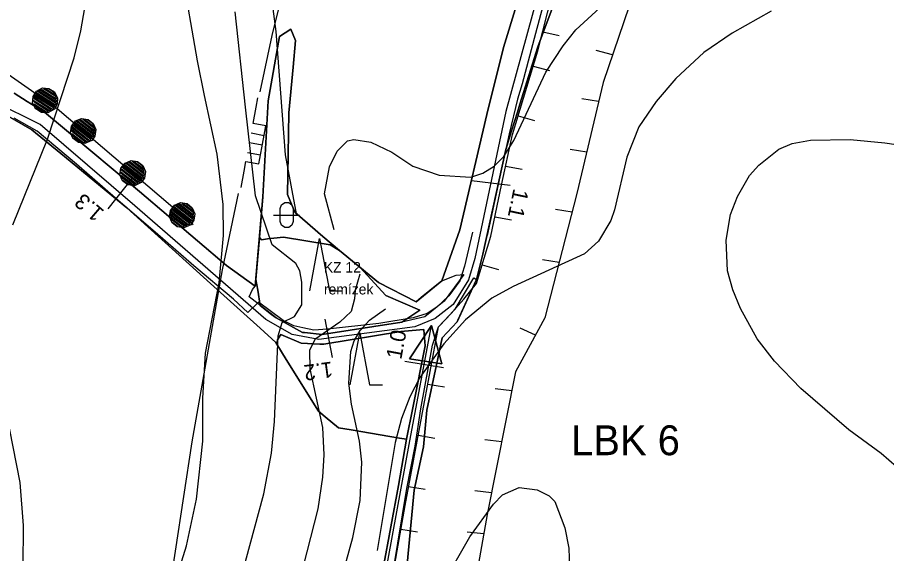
# Model space of a CAD drawing. Extents: x -645676 to -642474, y -1077513 to -1072613.
# Drawn here: x -644258.9 to -643924.4, y -1076253.6 to -1076047.4 of the extents above; entities that cross this region are included whole.
import ezdxf

# ---------------------------------------------------------------- set-up
doc = ezdxf.new("R2010")
doc.units = 0
for name, color, linetype in [('KRAJ_ZELEN_STAV', 7, 'Continuous'), ('Krajinn__zele____popis___stav', 7, 'Continuous'), ('KULTURY_STAV', 7, 'Continuous'), ('KULTURY_ZNACKY', 7, 'Continuous'), ('Lok_ln__biokoridor___navr_en_', 7, 'Continuous'), ('Odvodnen__cesty_pod_lnou_dren_____navr_en_', 7, 'Continuous'), ('Odvodnen__cesty_pr_kopem___navr_en_', 7, 'Continuous'), ('PC_NAVRH', 7, 'Continuous'), ('PC_STAN_NAVRH', 7, 'Continuous'), ('PLYNOVOD', 7, 'Continuous'), ('USES_BK_NAVRH', 7, 'Continuous'), ('USES_IP_NAVRH', 7, 'Continuous'), ('VRSTEVNICE', 7, 'Continuous')]:
    doc.layers.add(name, color=color, linetype=linetype)

# ---------------------------------------------------------------- blocks, each defined once
blk = doc.blocks.new('$944')
blk.add_line((0, 1.5), (0, -1.5))
blk = doc.blocks.new('$920')
for points in [[(0, 0), (-2.8, 1.25), (-2.8, -1.25), (0, 0)], [(-2.8, 1.25), (0, 0), (-2.8, -1.25), (-2.8, 1.25)]]:
    blk.add_lwpolyline(points)
blk = doc.blocks.new('3$0800')
blk.add_lwpolyline([(-0.75, 0), (0, 4), (0.75, 0), (1.75, 0)])
blk = doc.blocks.new('3$1600')
for points in [[(-0.5, 1.5), (-0.4, 1.79), (-0.15, 1.97), (0.16, 1.97), (0.41, 1.79), (0.51, 1.5), (0.51, 0.5), (0.41, 0.21), (0.16, 0.03), (-0.15, 0.03), (-0.4, 0.21), (-0.5, 0.5), (-0.5, 1.5)], [(-1, 1), (0.27, 1), (1, 1)]]:
    blk.add_lwpolyline(points)
blk = doc.blocks.new('2$1030')
blk.add_line((0, 0), (0, -0.5))
blk = doc.blocks.new('6$4100')
blk.add_lwpolyline([(0.19, 0.72), (0.53, 0.53), (0.72, 0.19), (0.72, -0.2), (0.53, -0.54), (0.19, -0.73), (-0.2, -0.73), (-0.54, -0.54), (-0.73, -0.2), (-0.75, 0.12), (-0.54, 0.52), (-0.2, 0.71), (0.19, 0.71), (0.2, 0.67), (-0.2, 0.67), (-0.36, 0.59), (0.36, 0.59), (0.44, 0.51), (-0.44, 0.51), (-0.52, 0.43), (0.52, 0.43), (0.6, 0.35), (-0.6, 0.35), (-0.6, 0.27), (0.6, 0.27), (0.68, 0.19), (-0.59, 0.19), (-0.68, 0.19), (-0.68, 0.11), (0.59, 0.11), (0.68, 0.11), (0.68, 0.03), (-0.59, 0.03), (-0.68, 0.03), (-0.68, -0.05), (0.59, -0.05), (0.68, -0.05), (0.68, -0.13), (-0.59, -0.13), (-0.68, -0.13), (-0.68, -0.21), (0.59, -0.21), (0.68, -0.21), (0.6, -0.29), (-0.6, -0.29), (-0.6, -0.37), (0.6, -0.37), (0.52, -0.45), (-0.52, -0.45), (-0.44, -0.53), (0.44, -0.53), (0.36, -0.61), (-0.36, -0.61), (-0.2, -0.69), (0.2, -0.69)])
blk = doc.blocks.new('6$3520')
for p, q in [((-0.76, 0), (-0.76, -1)), ((0, -1), (0, 0)), ((0.76, 0), (0.76, -1))]:
    blk.add_line(p, q)
blk.add_lwpolyline([(-3.5, 0), (-2.23, 0), (-1.48, 0), (-1.48, -1), (-0.21, -1), (1.06, -1), (1.5, -1), (1.5, 0), (2.77, 0), (3.5, 0)])

msp = doc.modelspace()

# ---------------------------------------------------------------- linework, layer by layer
at = {"layer": 'KRAJ_ZELEN_STAV'}
for points in [[(-644167.35, -1076150.76), (-644164.46, -1076116.34), (-644162.44, -1076079.41), (-644158.08, -1076054.68), (-644153.67, -1076051.97), (-644151.87, -1076056.3), (-644154.44, -1076084.07), (-644154.94, -1076115.51), (-644152.19, -1076122.23), (-644141.33, -1076131.67), (-644119.97, -1076149.38), (-644105.5, -1076156.74), (-644095.59, -1076148.67), (-644090.09, -1076146.58), (-644087.13, -1076146.25), (-644094.66, -1076156.57), (-644102.05, -1076162.51), (-644110.99, -1076164.6), (-644141.58, -1076169.31), (-644149.13, -1076168.54), (-644159.36, -1076162.99), (-644169.66, -1076154.89), (-644168.45, -1076151.98), (-644167.35, -1076150.76)], [(-644114.19, -1076259.66), (-644109.1, -1076228.56), (-644105.85, -1076212.33), (-644103.69, -1076197.94), (-644099.16, -1076173.48), (-644096.83, -1076166.36), (-644090.49, -1076159.63), (-644083.26, -1076147.58), (-644082.23, -1076148.18), (-644089.69, -1076164.46), (-644095.43, -1076170.57), (-644101.31, -1076198.48), (-644102.64, -1076212.56), (-644106.22, -1076229.19), (-644109.17, -1076260.32)]]:
    msp.add_lwpolyline(points, dxfattribs=at)
at = {"layer": 'KULTURY_STAV'}
for points in [[(-644260.19, -1076076.56), (-644255.1, -1076079.71), (-644250.1, -1076082.79), (-644248.52, -1076083.77), (-644240.78, -1076090.23), (-644211.91, -1076114.3), (-644178.41, -1076142.74), (-644167.35, -1076150.76), (-644167.13, -1076148.23), (-644167.13, -1076148.22), (-644166.33, -1076152.32), (-644165.51, -1076158.15), (-644161.1, -1076161.63), (-644159.36, -1076162.99), (-644149.13, -1076168.55), (-644148.47, -1076168.61), (-644141.58, -1076169.31), (-644110.99, -1076164.6), (-644110.97, -1076164.6), (-644104.09, -1076160.01), (-644117.17, -1076154.34), (-644127.14, -1076143.44), (-644119.97, -1076149.38), (-644105.5, -1076156.74), (-644103.46, -1076155.08), (-644100.16, -1076152.39), (-644095.59, -1076148.67), (-644088.67, -1076129.14), (-644078.26, -1076084.73), (-644071.86, -1076058.97), (-644057.9, -1076013.39)], [(-644057.9, -1076013.39), (-644071.86, -1076058.97), (-644078.26, -1076084.73), (-644088.67, -1076129.14), (-644095.59, -1076148.67), (-644100.16, -1076152.39), (-644103.46, -1076155.08), (-644105.5, -1076156.74), (-644119.97, -1076149.38), (-644127.14, -1076143.44), (-644134.92, -1076136.98), (-644134.94, -1076136.97), (-644141.33, -1076131.67), (-644152.19, -1076122.23), (-644154.94, -1076115.51), (-644154.82, -1076107.92), (-644154.44, -1076084.07), (-644152.81, -1076066.52), (-644151.87, -1076056.31), (-644153.67, -1076051.97), (-644158.08, -1076054.68), (-644162.44, -1076079.41), (-644164.47, -1076116.34), (-644165.78, -1076132.02), (-644167.13, -1076148.22), (-644167.13, -1076148.23), (-644167.35, -1076150.76), (-644178.41, -1076142.74), (-644211.91, -1076114.3), (-644240.78, -1076090.23), (-644248.52, -1076083.77), (-644250.1, -1076082.79), (-644255.1, -1076079.71), (-644260.19, -1076076.56)], [(-644048.37, -1076031.2), (-644058.62, -1076058.66), (-644065.52, -1076080.76), (-644066.49, -1076083.86), (-644068.73, -1076091.03), (-644070.97, -1076098.22), (-644079.76, -1076138.38), (-644082.09, -1076147.63), (-644082.23, -1076148.18), (-644085.8, -1076155.97), (-644089.4, -1076163.82), (-644089.69, -1076164.46), (-644093.55, -1076168.57), (-644095.43, -1076170.57), (-644097.64, -1076181.06), (-644101.31, -1076198.48), (-644102.64, -1076212.56), (-644106.22, -1076229.19), (-644109.17, -1076260.32)], [(-644109.17, -1076260.32), (-644106.22, -1076229.19), (-644102.64, -1076212.56), (-644101.31, -1076198.48), (-644097.64, -1076181.06), (-644095.43, -1076170.57), (-644093.55, -1076168.57), (-644089.69, -1076164.46), (-644089.4, -1076163.82), (-644085.8, -1076155.97), (-644082.23, -1076148.18), (-644082.09, -1076147.63), (-644079.76, -1076138.38), (-644070.97, -1076098.22), (-644068.73, -1076091.03), (-644066.49, -1076083.86), (-644065.52, -1076080.76), (-644058.62, -1076058.66), (-644048.37, -1076031.2)], [(-644153.67, -1076051.97), (-644151.87, -1076056.31), (-644152.81, -1076066.52), (-644154.44, -1076084.07), (-644154.82, -1076107.92), (-644154.94, -1076115.51), (-644152.19, -1076122.23), (-644141.33, -1076131.67), (-644134.94, -1076136.97), (-644134.92, -1076136.98), (-644138.54, -1076134.83), (-644156.52, -1076131.95), (-644162.62, -1076132.59), (-644164.97, -1076132.96), (-644165.78, -1076132.02), (-644164.47, -1076116.34), (-644162.44, -1076079.41), (-644158.08, -1076054.68), (-644153.67, -1076051.97)], [(-644118.1, -1076259.16), (-644112.19, -1076227.42), (-644109.13, -1076209.62), (-644106.67, -1076197.52), (-644102.03, -1076173.69), (-644102.49, -1076167.57), (-644102.5, -1076167.41), (-644104.06, -1076167.54), (-644111.38, -1076168.17), (-644140.99, -1076173.09), (-644142.52, -1076173.02), (-644149.64, -1076172.72), (-644157.52, -1076169.4), (-644157.73, -1076169.71), (-644158.81, -1076171.33), (-644159.07, -1076173.02), (-644159.49, -1076172.35), (-644165.51, -1076166.94), (-644173.04, -1076160.17), (-644184.58, -1076149.66), (-644216.77, -1076120.68), (-644242.18, -1076099.78), (-644253.28, -1076090.66), (-644263.37, -1076084.84)], [(-644263.37, -1076084.84), (-644253.28, -1076090.66), (-644242.18, -1076099.78), (-644216.77, -1076120.68), (-644184.58, -1076149.66), (-644173.04, -1076160.17), (-644165.51, -1076166.94), (-644159.49, -1076172.35), (-644159.07, -1076173.02), (-644155.43, -1076178.9), (-644143.05, -1076198.88), (-644140.47, -1076201.01), (-644140.46, -1076201.02), (-644135.28, -1076205.27), (-644130.52, -1076206.06), (-644130.51, -1076206.06), (-644111.8, -1076209.18), (-644109.13, -1076209.62), (-644112.19, -1076227.42), (-644118.1, -1076259.16)], [(-644156.52, -1076131.95), (-644138.54, -1076134.83), (-644134.92, -1076136.98), (-644127.14, -1076143.44), (-644117.17, -1076154.34), (-644104.09, -1076160.01), (-644110.97, -1076164.6), (-644110.99, -1076164.6), (-644141.58, -1076169.31), (-644148.47, -1076168.61), (-644149.13, -1076168.55), (-644159.36, -1076162.99), (-644161.09, -1076161.63), (-644165.51, -1076158.15), (-644166.33, -1076152.32), (-644167.13, -1076148.22), (-644165.78, -1076132.02), (-644164.97, -1076132.96), (-644162.62, -1076132.59), (-644156.52, -1076131.95)], [(-644102.5, -1076167.41), (-644102.49, -1076167.57), (-644102.03, -1076173.69), (-644106.67, -1076197.52), (-644109.13, -1076209.62), (-644111.8, -1076209.18), (-644130.51, -1076206.06), (-644130.52, -1076206.06), (-644135.28, -1076205.27), (-644140.46, -1076201.02), (-644140.47, -1076201.01), (-644143.05, -1076198.88), (-644155.43, -1076178.9), (-644159.07, -1076173.02), (-644158.81, -1076171.34), (-644157.73, -1076169.71), (-644157.52, -1076169.4), (-644149.64, -1076172.72), (-644142.52, -1076173.02), (-644140.99, -1076173.09), (-644111.38, -1076168.17), (-644104.06, -1076167.54), (-644102.5, -1076167.41)]]:
    msp.add_lwpolyline(points, dxfattribs=at)
at = {"layer": 'Odvodnen__cesty_pod_lnou_dren_____navr_en_'}
msp.add_lwpolyline([(-644083.78, -1076130.04), (-644086.87, -1076143.11), (-644088.59, -1076148.75), (-644092.87, -1076154.43), (-644097.34, -1076158.67), (-644101.23, -1076161.25), (-644106.56, -1076162.97), (-644119.8, -1076165.09), (-644139.62, -1076167.27), (-644144.84, -1076167.61), (-644149.08, -1076166.81), (-644152.52, -1076166.01), (-644156.64, -1076163.89), (-644166.15, -1076156.88), (-644170.21, -1076160.87), (-644175.78, -1076155.78), (-644191.04, -1076142.92), (-644205.82, -1076129.93), (-644221.09, -1076116.86), (-644236.15, -1076103.8), (-644251.27, -1076091.08), (-644260.08, -1076086.2)], dxfattribs=at)
at = {"layer": 'Odvodnen__cesty_pr_kopem___navr_en_'}
msp.add_lwpolyline([(-644023.83, -1075949.97), (-644026.63, -1075959.61), (-644034.15, -1075978.39), (-644041.96, -1075996.64), (-644045.27, -1076004.69), (-644049.01, -1076015.17), (-644054.35, -1076034.31), (-644059.51, -1076053.59), (-644064.72, -1076072.91), (-644066.41, -1076078.85), (-644069.69, -1076092.14), (-644073.87, -1076111.64), (-644078.09, -1076131.22)], dxfattribs=at)
at = {"layer": 'PC_NAVRH'}
for points in [[(-643980.8, -1075688.59), (-643993.21, -1075785.86), (-644010.28, -1075875.28), (-644023.88, -1075939.56), (-644035.31, -1075972.69), (-644046.94, -1075998.73), (-644056.79, -1076032.05), (-644070.99, -1076083.52), (-644082.81, -1076140.12), (-644085.3, -1076148.31), (-644091.25, -1076157.77), (-644098.13, -1076163.17), (-644105.97, -1076166.41), (-644142.95, -1076171.3), (-644153.17, -1076169.36), (-644163.3, -1076163.53), (-644213.71, -1076119.84), (-644250.14, -1076088.62), (-644267.83, -1076079.85)], [(-644139.39, -1076495.57), (-644142.46, -1076477.03), (-644143.16, -1076449.01), (-644143.37, -1076421.26), (-644138.79, -1076373.8), (-644124.24, -1076299.79), (-644107.91, -1076210.28), (-644099.52, -1076165.84)]]:
    msp.add_lwpolyline(points, dxfattribs=at)
at = {"layer": 'PLYNOVOD'}
for points in [[(-644165.44, -1076076.01), (-644160.84, -1076054.32), (-644153.66, -1076025.19)], [(-644203.86, -1076296.81), (-644201.22, -1076273.74), (-644191.65, -1076210.65), (-644179.98, -1076144.48), (-644173.75, -1076115.13)]]:
    msp.add_lwpolyline(points, dxfattribs=at)
at = {"layer": 'USES_BK_NAVRH'}
for points in [[(-644001.62, -1075978.91), (-644033.51, -1076072.43), (-644043.56, -1076115.08), (-644055.98, -1076162.98), (-644067.17, -1076183.7), (-644078.1, -1076238.58), (-644098.86, -1076355.9), (-644115.99, -1076456.27), (-644109.33, -1076488.41)], [(-644148.37, -1076488.7), (-644138.52, -1076392.37), (-644130.82, -1076353.27), (-644122.99, -1076310.72), (-644109.72, -1076235.13), (-644096.83, -1076166.36), (-644093.66, -1076163), (-644087.08, -1076155.79), (-644082.23, -1076149.72), (-644076.69, -1076131.48), (-644072.64, -1076111.89), (-644068.4, -1076092.44), (-644058.62, -1076060.2), (-644047.3, -1076015.73)]]:
    msp.add_lwpolyline(points, dxfattribs=at)
at = {"layer": 'USES_IP_NAVRH'}
msp.add_lwpolyline([(-644191.24, -1076127.18), (-644243.65, -1076082.59), (-644262.38, -1076069.4), (-644280.99, -1076068.78), (-644299.22, -1076070.01)], dxfattribs=at)
at = {"layer": 'VRSTEVNICE'}
for points in [[(-644260.64, -1076127.22), (-644247.32, -1076094.2), (-644237.04, -1076062.92), (-644234.43, -1076052.49), (-644231.82, -1076036.85), (-644229.8, -1076015.99), (-644230.23, -1076004.99), (-644232.11, -1075988.48), (-644237.47, -1075960.96), (-644243.84, -1075938.95), (-644247.47, -1075916.94), (-644248.62, -1075900.43), (-644247.18, -1075878.41), (-644247.18, -1075867.41), (-644252.1, -1075830.04), (-644257.02, -1075803.98), (-644270.78, -1075750.68)], [(-644262.24, -1076457.55), (-644251.38, -1076446.55), (-644243.27, -1076435.54), (-644237.33, -1076425.26), (-644229.07, -1076404.98), (-644222.56, -1076384.71), (-644217.63, -1076366.46), (-644213.29, -1076344.16), (-644206.34, -1076288.84), (-644203.44, -1076278.41), (-644199.24, -1076267.98), (-644193.88, -1076250.61), (-644189.97, -1076232.65), (-644187.51, -1076210.35), (-644187.51, -1076193.84), (-644186.5, -1076176.46), (-644181.28, -1076149.52), (-644179.54, -1076131.27), (-644179.69, -1076119.4), (-644182.01, -1076099.99), (-644186.93, -1076077.4), (-644189.54, -1076064.08), (-644195.62, -1076029.32)], [(-644136.95, -1076129.1), (-644140.73, -1076115.2), (-644138.85, -1076104.92), (-644135.81, -1076098.83), (-644131.9, -1076094.92), (-644129.44, -1076094.34), (-644122.92, -1076095.36), (-644114.81, -1076099.27), (-644106.7, -1076104.63), (-644096.56, -1076108.1), (-644084.4, -1076108.82), (-644079.76, -1076107.23), (-644075.42, -1076104.63), (-644071.65, -1076100.86), (-644067.89, -1076094.78), (-644055.58, -1076068.42), (-644048.92, -1076058.28), (-644043.99, -1076052.2), (-644031.68, -1076040.9)], [(-644167.24, -1076116), (-644171.11, -1076081.9), (-644175.05, -1076045.25)], [(-644151.36, -1076123.59), (-644155.79, -1076100.28), (-644159.27, -1076052.78), (-644160.43, -1076044.09)], [(-643968.83, -1076044.96), (-643983.89, -1076053.5), (-643994.75, -1076060.89), (-644005.47, -1076070.88), (-644013.14, -1076079.72), (-644019.81, -1076089.42), (-644024.44, -1076101.15), (-644029.07, -1076121.42), (-644030.52, -1076125.48), (-644035.3, -1076133.44), (-644040.66, -1076138.37), (-644068.18, -1076150.82), (-644076.29, -1076155.31), (-644086.42, -1076163.71), (-644094.82, -1076172.98), (-644104.09, -1076185.87), (-644107.86, -1076193.26), (-644111.04, -1076201.66), (-644113.51, -1076210.92), (-644120.48, -1076252.4)], [(-643917.71, -1076222.8), (-643926.54, -1076215.12), (-643939, -1076206), (-643957.39, -1076190.07), (-643967.53, -1076179.64), (-643974.19, -1076170.95), (-643980.7, -1076159.37), (-643983.6, -1076152.13), (-643985.63, -1076144.89), (-643986.21, -1076133.01), (-643984.47, -1076123.16), (-643981.86, -1076116.21), (-643977.23, -1076108.25), (-643973.61, -1076104.19), (-643965.93, -1076098.11), (-643960.72, -1076095.94), (-643953.77, -1076094.63), (-643938.42, -1076094.34), (-643925.09, -1076095.65), (-643897.29, -1076099.7)], [(-644212.71, -1076482.03), (-644206.92, -1076464.65), (-644197.94, -1076428.16), (-644193.16, -1076402.38), (-644187.36, -1076358.93), (-644183.02, -1076331.42), (-644179.54, -1076299.55), (-644176.65, -1076279.86), (-644171.14, -1076256.69), (-644164.05, -1076230.62), (-644161.15, -1076214.98), (-644159.99, -1076202.81), (-644158.54, -1076169.79), (-644156.95, -1076164.73), (-644152.32, -1076162.41), (-644149.42, -1076157.92), (-644149.42, -1076149.23), (-644150.15, -1076144.89), (-644151.74, -1076141.99), (-644160.87, -1076134.82), (-644167.24, -1076116)], [(-644127.07, -1076146.07), (-644128.96, -1076152.26), (-644129.15, -1076155.6), (-644130.45, -1076160.53), (-644134.79, -1076164.58), (-644144.5, -1076171.24), (-644146.52, -1076175.44), (-644146.38, -1076182.54), (-644141.46, -1076205.13), (-644141.02, -1076215.56), (-644141.46, -1076224.25), (-644143.34, -1076236.41), (-644157.53, -1076292.02), (-644165.06, -1076328.52), (-644170.42, -1076358.93), (-644174.76, -1076394.27), (-644176.65, -1076425.84), (-644179.69, -1076451.91), (-644184.61, -1076476.24), (-644192.14, -1076521.42)], [(-644160.86, -1076435.98), (-644161.15, -1076417.73), (-644159.27, -1076398.03), (-644157.68, -1076389.92), (-644148.55, -1076357.48), (-644138.56, -1076284.2), (-644134.65, -1076265.09), (-644129.87, -1076247.42), (-644126.97, -1076233.23), (-644126.39, -1076218.46), (-644127.26, -1076210.35), (-644130.3, -1076196.15), (-644131.32, -1076188.04), (-644130.59, -1076175.88), (-644129.29, -1076171.82), (-644126.97, -1076167.77), (-644123.35, -1076163.86), (-644117.25, -1076159.47)], [(-644262.53, -1076305.64), (-644258.04, -1076274.36), (-644256.73, -1076258.72), (-644256.59, -1076242.78), (-644257.89, -1076226.27), (-644263.25, -1076198.76)], [(-644094.97, -1076264.8), (-644084.83, -1076247.13), (-644075.71, -1076234.53), (-644072.23, -1076231.05), (-644065.86, -1076228.16), (-644058.91, -1076229.03), (-644054.27, -1076231.34), (-644052.1, -1076233.52), (-644048.19, -1076243.65), (-644046.74, -1076251.47), (-644046.16, -1076266.83)]]:
    msp.add_lwpolyline(points, dxfattribs=at)

# ---------------------------------------------------------------- block references
at = {"layer": 'KULTURY_ZNACKY', "xscale": 5, "yscale": 5}
for name, p in [('3$1600', (-644155.29, -1076128.38)), ('3$0800', (-644142.59, -1076152.48)), ('3$0800', (-644127.15, -1076188.71))]:
    msp.add_blockref(name, p, dxfattribs=at)
at = {"layer": 'PC_STAN_NAVRH', "xscale": 5}
for name, p, yscale, rotation in [('$944', (-644219.27, -1076115.08), 5, 141.82779899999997), ('$944', (-644076.75, -1076111.13), 4.999999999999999, -97.29589299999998), ('$944', (-644139.1, -1076170.8), 5, -169.19209), ('$920', (-644099.52, -1076165.84), 5.000000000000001, 80.681356), ('$944', (-644102.35, -1076180.83), 5.000000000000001, 80.681356)]:
    msp.add_blockref(name, p, dxfattribs=dict(at, yscale=yscale, rotation=rotation))
at = {"layer": 'PLYNOVOD', "xscale": 5, "yscale": 5, "rotation": 79.376265}
msp.add_blockref('6$3520', (-644169.6, -1076095.57), dxfattribs=at)
at = {"layer": 'USES_BK_NAVRH'}
for p, xscale, yscale, rotation in [((-644056.77, -1076052.93), 12.999999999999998, 13.000000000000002, 77.040795), ((-644029.86, -1076061.73), 13, 13.000000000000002, -104.44687899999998), ((-644060.42, -1076066.12), 13, 13, 74.407425), ((-644035.23, -1076079.73), 13.000000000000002, 12.999999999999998, -98.79006900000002), ((-644066.22, -1076085.26), 13, 13, 74.407425), ((-644039.82, -1076099.2), 13.000000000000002, 12.999999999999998, -98.79006900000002), ((-644071.04, -1076104.57), 12.999999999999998, 13, 79.035912), ((-644045.45, -1076122.34), 13.000000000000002, 12.999999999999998, -100.071927), ((-644075.17, -1076124.13), 13, 13.000000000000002, 79.701178), ((-644080.05, -1076142.55), 12.999999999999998, 13.000000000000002, 74.383401), ((-644050.46, -1076141.7), 13.000000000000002, 12.999999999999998, -100.071927), ((-644059.54, -1076169.58), 13, 12.999999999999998, -114.15179800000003), ((-644100.97, -1076188.45), 12.999999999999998, 13.000000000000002, 80.76866800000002), ((-644068.63, -1076191.05), 13.000000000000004, 12.999999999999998, -96.75011500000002), ((-644104.66, -1076208.1), 12.999999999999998, 13.000000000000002, 80.76866800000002), ((-644072.54, -1076210.67), 13.000000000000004, 12.999999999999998, -96.75011500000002), ((-644108.34, -1076227.76), 12.999999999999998, 13.000000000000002, 80.76866800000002), ((-644076.45, -1076230.28), 13.000000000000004, 12.999999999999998, -96.75011500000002), ((-644111.32, -1076244.24), 12.999999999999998, 13.000000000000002, 81.439222), ((-644079.41, -1076245.96), 12.999999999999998, 13.000000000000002, -95.495526)]:
    msp.add_blockref('2$1030', p, dxfattribs=dict(at, xscale=xscale, yscale=yscale, rotation=rotation))
at = {"layer": 'USES_IP_NAVRH'}
for p, xscale, yscale, rotation in [((-644248.27, -1076079.34), 6.5, 6.5, 147.383426), ((-644233.62, -1076091.12), 6.499999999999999, 6.500000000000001, 142.048345), ((-644214.58, -1076107.32), 6.499999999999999, 6.500000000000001, 142.048345), ((-644195.54, -1076123.52), 6.499999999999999, 6.500000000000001, 142.048345)]:
    msp.add_blockref('6$4100', p, dxfattribs=dict(at, xscale=xscale, yscale=yscale, rotation=rotation))

# ---------------------------------------------------------------- texts
at = {"layer": 'Krajinn__zele____popis___stav'}
for s, p in [('KZ 12', (-644140.99, -1076145.5)), ('remízek', (-644140.93, -1076153.93))]:
    msp.add_text(s, height=4, dxfattribs=at).set_placement(p)
at = {"layer": 'Lok_ln__biokoridor___navr_en_'}
msp.add_text('LBK 6', height=11.5, dxfattribs=at).set_placement((-644045.85, -1076215.76))
at = {"layer": 'PC_STAN_NAVRH'}
for s, rotation, p in [('1.3', 139.401, (-644225.12, -1076121.92)), ('1.1', 258.175, (-644067.94, -1076112.96)), ('1.0', 79.297, (-644111.19, -1076179.17)), ('1.2', 187.529, (-644137.91, -1076179.72))]:
    msp.add_text(s, height=6, rotation=rotation, dxfattribs=at).set_placement(p)

doc.saveas('drawing.dxf')
